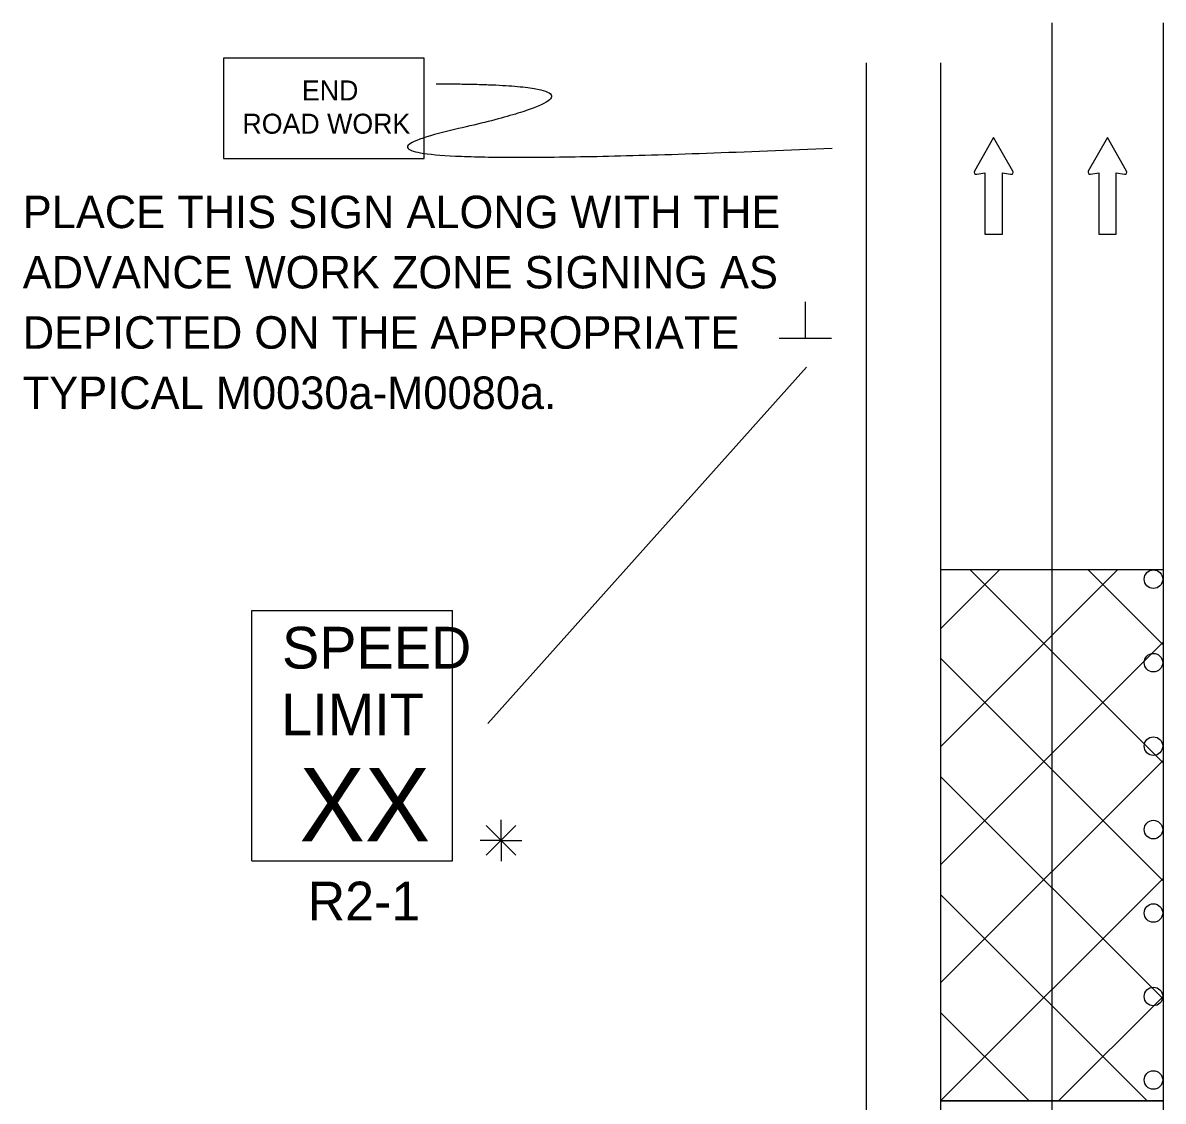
# Model space of a CAD drawing. Extents: x 16735 to 18480, y 5523 to 6928.
# Drawn here: x 16734.8 to 16980.6, y 6695.3 to 6927.8 of the extents above; entities that cross this region are included whole.
import ezdxf

# ---------------------------------------------------------------- set-up
doc = ezdxf.new("R2010")
doc.units = 0
for name, color, linetype in [('ALI_LEGAL_EX', 7, 'Continuous'), ('MT_SCRATCH_LEVEL_A', 7, 'Continuous'), ('MT_SCRATCH_LEVEL_E', 7, 'Continuous'), ('PAVT_EDGE_EX', 7, 'Continuous'), ('TRAFFIC_SIGNS_PR', 7, 'Continuous'), ('TYPICAL_TEXT_DIMEN_PR', 7, 'Continuous')]:
    doc.layers.add(name, color=color, linetype=linetype)

msp = doc.modelspace()

# ---------------------------------------------------------------- linework, layer by layer
at = {"layer": 'ALI_LEGAL_EX'}
for p, q in [((16956.63, 6927.83), (16956.63, 6083.69)), ((16980.63, 6927.83), (16980.63, 6083.69))]:
    msp.add_line(p, q, dxfattribs=at)
for points in [[(16956.63, 6919.19), (16956.63, 6902.83)], [(16980.63, 6919.19), (16980.63, 6902.83)], [(16956.63, 6827.83), (16956.63, 6802.83)], [(16980.63, 6827.83), (16980.63, 6802.83)], [(16956.63, 6727.83), (16956.63, 6702.83)], [(16980.63, 6727.83), (16980.63, 6702.83)]]:
    msp.add_lwpolyline(points, dxfattribs=at)
at = {"layer": 'MT_SCRATCH_LEVEL_A'}
for p, q in [((16980.63, 6809.85), (16932.63, 6809.85)), ((16980.63, 6695.32), (16932.63, 6695.32))]:
    msp.add_line(p, q, dxfattribs=at)
at = {"layer": 'MT_SCRATCH_LEVEL_E'}
for p, q in [((16944.07, 6903.1), (16939.96, 6895.86)), ((16948.22, 6895.86), (16944.07, 6903.1)), ((16968.6, 6903.1), (16964.49, 6895.86)), ((16972.75, 6895.86), (16968.6, 6903.1)), ((16940.44, 6895.17), (16942.22, 6895.49)), ((16942.22, 6895.49), (16942.22, 6882.23)), ((16945.96, 6882.23), (16945.96, 6895.49)), ((16945.96, 6895.49), (16947.74, 6895.17)), ((16964.97, 6895.17), (16966.75, 6895.49)), ((16966.75, 6895.49), (16966.75, 6882.23)), ((16970.49, 6882.23), (16970.49, 6895.49)), ((16970.49, 6895.49), (16972.27, 6895.17)), ((16942.22, 6882.23), (16945.96, 6882.23)), ((16966.75, 6882.23), (16970.49, 6882.23))]:
    msp.add_line(p, q, dxfattribs=at)
for centre, start, end in [((16940.37, 6895.63), 150.4248, 279.9638), ((16947.81, 6895.63), 260.0362, 29.7731), ((16964.9, 6895.63), 150.4248, 279.9638), ((16972.34, 6895.63), 260.0362, 29.7731)]:
    msp.add_arc(centre, 0.463, start, end, dxfattribs=at)
at = {"layer": 'PAVT_EDGE_EX'}
for p, q in [((16916.63, 6919.19), (16916.63, 6059.77)), ((16932.63, 6919.19), (16932.63, 6059.77)), ((16980.63, 6809.85), (16932.63, 6809.85)), ((16932.63, 6809.85), (16932.63, 6695.32)), ((16932.63, 6797.14), (16945.35, 6809.85)), ((16932.63, 6771.68), (16970.8, 6809.85)), ((16980.63, 6768.23), (16939.01, 6809.85)), ((16980.63, 6793.69), (16964.47, 6809.85)), ((16932.63, 6746.23), (16980.63, 6794.23)), ((16980.63, 6742.78), (16932.63, 6790.78)), ((16932.63, 6720.77), (16980.63, 6768.77)), ((16980.63, 6717.32), (16932.63, 6765.32)), ((16932.63, 6695.32), (16980.63, 6743.32)), ((16977.18, 6695.32), (16932.63, 6739.86)), ((16958.09, 6695.32), (16980.63, 6717.86)), ((16951.73, 6695.32), (16932.63, 6714.41)), ((16932.63, 6695.32), (16980.63, 6695.32)), ((16980.63, 6695.32), (16932.63, 6695.32)), ((16932.63, 6695.32), (16932.63, 6665.89)), ((16932.63, 6695.32), (16932.63, 6695.32))]:
    msp.add_line(p, q, dxfattribs=at)
at = {"layer": 'TRAFFIC_SIGNS_PR'}
for p, q in [((16784.21, 6801.11), (16827.41, 6801.11)), ((16784.21, 6747.11), (16784.21, 6801.11)), ((16827.41, 6747.11), (16827.41, 6801.11)), ((16784.21, 6747.11), (16827.41, 6747.11))]:
    msp.add_line(p, q, dxfattribs=at)
msp.add_lwpolyline([(16778.1, 6898.58), (16821.31, 6898.58), (16821.31, 6920.18), (16778.1, 6920.18)], close=True, dxfattribs=at)
for centre in [(16978.53, 6807.84), (16978.53, 6789.84), (16978.53, 6771.84), (16978.53, 6753.84), (16978.53, 6735.84), (16978.53, 6717.84), (16978.53, 6699.84)]:
    msp.add_circle(centre, 2, dxfattribs=at)
msp.add_open_spline([(16823.94, 6914.67), (16871.17, 6914.67), (16786.15, 6895.33), (16909.25, 6900.82)], degree=2, dxfattribs=at)
at = {"layer": 'TYPICAL_TEXT_DIMEN_PR'}
for p, q in [((16903.51, 6859.85), (16903.51, 6867.64)), ((16897.88, 6859.85), (16909.13, 6859.85)), ((16835.02, 6776.73), (16903.75, 6853.59)), ((16837.92, 6751.51), (16837.92, 6755.96)), ((16834.73, 6754.69), (16841.11, 6748.32)), ((16841.11, 6754.69), (16834.73, 6748.32)), ((16837.92, 6751.51), (16833.39, 6751.51)), ((16837.92, 6751.51), (16841.11, 6751.51)), ((16837.92, 6751.51), (16842.4, 6751.51)), ((16837.92, 6751.51), (16837.92, 6747.01))]:
    msp.add_line(p, q, dxfattribs=at)

# ---------------------------------------------------------------- texts
at = {"layer": 'TRAFFIC_SIGNS_PR'}
for s, height, p in [('END', 4.31, (16794.98, 6911.1)), ('ROAD WORK', 4.31, (16782.16, 6903.92)), ('PLACE THIS SIGN ALONG WITH THE', 7, (16734.8, 6883.55)), ('ADVANCE WORK ZONE SIGNING AS', 7, (16734.8, 6870.55)), ('DEPICTED ON THE APPROPRIATE', 7, (16734.8, 6857.55)), ('TYPICAL M0030a-M0080a.', 7, (16734.8, 6844.55)), ('SPEED', 9, (16790.69, 6788.57)), ('LIMIT', 9, (16790.51, 6774.18)), ('XX', 15.785, (16794.46, 6751.33)), ('R2-1', 8.37, (16796.22, 6734.24))]:
    msp.add_text(s, height=height, dxfattribs=at).set_placement(p)

doc.saveas('drawing.dxf')
